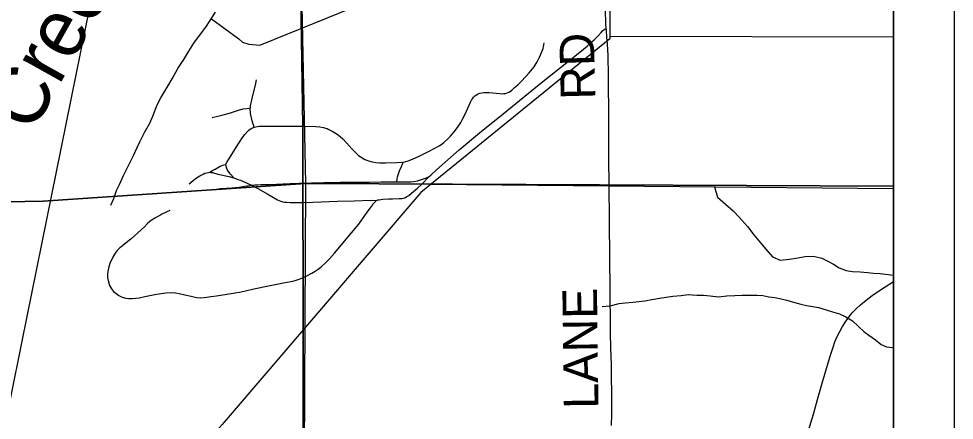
# Model space of a CAD drawing. Extents: x 0 to 34, y 0 to 22.
# Drawn here: x 7.463 to 9, y 15.878 to 16.538 of the extents above; entities that cross this region are included whole.
import ezdxf

# ---------------------------------------------------------------- set-up
doc = ezdxf.new("R2010")
doc.units = 0
for name, color, linetype in [('GM_X_County_Road', 7, 'Continuous'), ('GM_X_County_Road_Text', 7, 'Continuous'), ('GM_X_Major_River_Text', 7, 'Continuous'), ('GM_X_Minor_River', 7, 'Continuous'), ('GM_X_Rail_Line', 7, 'Continuous'), ('GM_X_Section', 7, 'Continuous'), ('GM_X_State_Route', 7, 'Continuous'), ('GM_X_Township_Road', 7, 'Continuous'), ('GM_X_Unincorporated', 7, 'Continuous'), ('SH_Data', 7, 'Continuous')]:
    doc.layers.add(name, color=color, linetype=linetype)

msp = doc.modelspace()

# ---------------------------------------------------------------- linework, layer by layer
at = {"layer": 'GM_X_County_Road'}
for points in [[(8.4282, 16.5223), (8.4276, 16.5297), (8.4273, 16.5364), (8.4269, 16.546), (8.4267, 16.5738), (8.4266, 16.6455), (8.4263, 16.7142), (8.4261, 16.7744)], [(8.4371, 15.8698), (8.4374, 15.8884), (8.4375, 15.9008), (8.4375, 15.9101), (8.4373, 15.9225), (8.4369, 15.9504), (8.4368, 15.9694), (8.436, 15.997), (8.4355, 16.0218), (8.4351, 16.0371), (8.435, 16.0556), (8.4348, 16.068), (8.4345, 16.0959), (8.434, 16.1425), (8.4335, 16.2076), (8.4332, 16.2635), (8.4326, 16.3101), (8.4326, 16.3721), (8.432, 16.4435), (8.4314, 16.4777), (8.4303, 16.4962), (8.4294, 16.5078), (8.4285, 16.5185), (8.4282, 16.5223)]]:
    msp.add_lwpolyline(points, dxfattribs=at)
at = {"layer": 'GM_X_Minor_River'}
for p, q in [((8.4339, 16.5096), (8.9, 16.5083)), ((8.1399, 16.2661), (8.9, 16.2594))]:
    msp.add_line(p, q, dxfattribs=at)
for points in [[(8.4344, 16.8906), (8.4339, 16.505), (8.1234, 16.2526), (7.7972, 15.8716), (7.3114, 15.3314), (7.166, 15.2871), (6.9088, 15.1189), (6.3982, 15.0073)], [(7.7796, 16.5378), (7.8248, 16.5051), (7.8305, 16.4998), (7.8411, 16.4965), (7.8593, 16.4947), (8.2339, 16.6471), (8.2403, 16.6506), (8.2527, 16.6612), (8.2735, 16.7521)], [(7.6143, 16.232), (7.6192, 16.2427), (7.6236, 16.2556), (7.6285, 16.2659), (7.6353, 16.2803), (7.6401, 16.2902), (7.6469, 16.3035), (7.6514, 16.3134), (7.6577, 16.3263), (7.6622, 16.3358), (7.6705, 16.3522), (7.6783, 16.3667), (7.6836, 16.3781), (7.6903, 16.3967), (7.6967, 16.4081), (7.7079, 16.4275), (7.7151, 16.4393), (7.7244, 16.4565), (7.7342, 16.4713), (7.7425, 16.485), (7.7507, 16.498), (7.7631, 16.5147), (7.7703, 16.5242), (7.7778, 16.5349), (7.7864, 16.549)], [(8.6059, 16.262), (8.6111, 16.2451), (8.6244, 16.2334), (8.6365, 16.2224), (8.6464, 16.2118), (8.6601, 16.1967), (8.6708, 16.1831), (8.6818, 16.1699), (8.6906, 16.1597), (8.7016, 16.1468), (8.7141, 16.1416), (8.7292, 16.1431), (8.7398, 16.1447), (8.7549, 16.1474), (8.7689, 16.1479), (8.7822, 16.1445), (8.792, 16.1396), (8.8015, 16.1348), (8.811, 16.1291), (8.8224, 16.1246), (8.833, 16.1228), (8.8455, 16.1221), (8.8576, 16.121), (8.8674, 16.1199), (8.878, 16.1196), (8.9, 16.1169)], [(8.4217, 16.0653), (8.4346, 16.0663), (8.4494, 16.0704), (8.4596, 16.0712), (8.4717, 16.0726), (8.4819, 16.0737), (8.4917, 16.0744), (8.5031, 16.0766), (8.5163, 16.0788), (8.5269, 16.0807), (8.5375, 16.0822), (8.5511, 16.0832), (8.5629, 16.0851), (8.5768, 16.0842), (8.5882, 16.0842), (8.5992, 16.083), (8.6128, 16.0814), (8.6264, 16.0829), (8.6396, 16.0836), (8.6513, 16.0839), (8.6634, 16.0838), (8.6755, 16.0841), (8.6854, 16.0833), (8.6956, 16.0814), (8.705, 16.0802), (8.7156, 16.0779), (8.7251, 16.0755), (8.736, 16.0724), (8.7477, 16.0694), (8.7572, 16.067), (8.7674, 16.0651), (8.7768, 16.0635), (8.7893, 16.0597), (8.8002, 16.0566), (8.8116, 16.0531), (8.8218, 16.0481), (8.8327, 16.0416), (8.8433, 16.0321), (8.8512, 16.0245), (8.8598, 16.0183), (8.8704, 16.0103), (8.8798, 16.0031), (8.8889, 15.9988), (8.8983, 15.9977), (8.9, 15.9974)]]:
    msp.add_lwpolyline(points, dxfattribs=at)
at = {"layer": 'GM_X_Rail_Line'}
msp.add_lwpolyline([(6.4606, 14.1), (6.4571, 14.1954), (6.4477, 14.4405), (6.4524, 14.5081), (6.4637, 14.5568), (6.4857, 14.6083), (6.5473, 14.6979), (6.8861, 15.1309), (7.2406, 15.5724), (7.3338, 15.6825), (7.3851, 15.7562), (7.4225, 15.8224), (7.4495, 15.9132), (7.4686, 16.0084), (7.5816, 16.5648), (7.6436, 16.8869), (7.6684, 17.0095), (7.6975, 17.0913), (7.758, 17.2454), (8.0083, 17.8807), (8.1494, 18.2455), (8.2773, 18.5592), (8.2934, 18.6184), (8.454, 19.2815)], dxfattribs=at)
at = {"layer": 'GM_X_Section'}
for points in [[(6.9237, 17.2428), (7.9201, 17.2543), (7.92, 16.958), (7.9341, 16.2671), (7.503, 16.2382), (6.9303, 16.2282)], [(7.9341, 16.2671), (7.9294, 15.2601), (6.9531, 15.2604), (6.9228, 15.2602), (6.9303, 16.2282), (7.503, 16.2382)]]:
    msp.add_lwpolyline(points, close=True, dxfattribs=at)
at = {"layer": 'GM_X_State_Route'}
msp.add_lwpolyline([(8.7579, 15.8529), (8.7685, 15.8886), (8.7755, 15.9124), (8.7832, 15.9393), (8.7962, 15.9839), (8.8008, 15.9987), (8.804, 16.0074), (8.8077, 16.0158), (8.8118, 16.0241), (8.8164, 16.0322), (8.8213, 16.0401), (8.8266, 16.0476), (8.8325, 16.0548), (8.8389, 16.0615), (8.8457, 16.0678), (8.8552, 16.0758), (8.865, 16.0832), (8.8804, 16.0937), (8.9, 16.1066)], dxfattribs=at)
at = {"layer": 'GM_X_Township_Road'}
for points in [[(5.7675, 15.2711), (6.9226, 15.2644), (7.9283, 15.2595), (7.9306, 15.7658), (7.9301, 16.1134), (7.9298, 16.2367), (7.9298, 16.2686), (7.9297, 16.3619), (7.9163, 17.252), (8.4218, 17.2637), (8.9, 17.2634), (8.9, 20.9)], [(7.9303, 16.1128), (7.9366, 16.1156), (7.9448, 16.1199), (7.9502, 16.1231), (7.9552, 16.1267), (7.9601, 16.1306), (7.9669, 16.1369), (7.9735, 16.1436), (7.9817, 16.1529), (8.0099, 16.1861), (8.0216, 16.2006), (8.0317, 16.2146), (8.0361, 16.2207), (8.0406, 16.2271), (8.0429, 16.2303), (8.0455, 16.2338), (8.0478, 16.2363), (8.0489, 16.2375), (8.0498, 16.2384), (8.051, 16.2397), (8.0531, 16.2403), (8.0552, 16.2407), (8.0582, 16.2412), (8.0615, 16.2415), (8.0709, 16.2421), (8.0771, 16.2423), (8.0882, 16.2428), (8.0925, 16.243), (8.0953, 16.2435), (8.0983, 16.2446), (8.1007, 16.2458), (8.1037, 16.2478), (8.1086, 16.2515), (8.118, 16.2595), (8.1249, 16.2658), (8.1374, 16.2786), (8.1401, 16.2813), (8.1492, 16.2897), (8.1867, 16.3224), (8.22, 16.3505), (8.2589, 16.3817), (8.3215, 16.4328), (8.3847, 16.483), (8.3907, 16.4878), (8.3971, 16.4931), (8.4015, 16.4972), (8.4084, 16.5035), (8.4149, 16.5102), (8.4198, 16.5156), (8.4222, 16.5181), (8.4248, 16.5202), (8.4266, 16.5215), (8.4282, 16.5223)], [(7.9299, 16.3614), (7.9328, 16.3613), (7.9514, 16.3609), (7.9576, 16.3603), (7.9637, 16.3593), (7.9668, 16.3585), (7.9697, 16.3575), (7.9726, 16.3563), (7.9781, 16.3534), (7.986, 16.3484), (7.9909, 16.3446), (7.9956, 16.3405), (8.002, 16.3337), (8.0102, 16.3244), (8.0168, 16.3177), (8.0214, 16.3136), (8.0239, 16.3117), (8.0265, 16.3099), (8.0291, 16.3084), (8.0319, 16.3069), (8.0348, 16.3057), (8.0377, 16.3046), (8.0437, 16.3031), (8.0499, 16.3021), (8.0561, 16.3015), (8.0654, 16.3014), (8.0841, 16.3017), (8.0934, 16.3023), (8.0945, 16.3024), (8.099, 16.3035), (8.103, 16.3047), (8.1097, 16.3071), (8.1222, 16.3128), (8.1331, 16.3183), (8.1373, 16.3204), (8.1457, 16.3246), (8.1539, 16.3293), (8.1565, 16.3309), (8.1613, 16.3345), (8.1681, 16.3406), (8.1724, 16.345), (8.1785, 16.3521), (8.1841, 16.3596), (8.1892, 16.3676), (8.1922, 16.373), (8.1964, 16.3814), (8.2053, 16.4012), (8.2068, 16.404), (8.2084, 16.4066), (8.2104, 16.4091), (8.2126, 16.4112), (8.215, 16.4131), (8.2178, 16.4145), (8.2207, 16.4156), (8.2238, 16.4162), (8.2269, 16.4167), (8.23, 16.4168), (8.2359, 16.4167), (8.2532, 16.415), (8.2564, 16.4149), (8.2595, 16.415), (8.2625, 16.4154), (8.2654, 16.4163), (8.2682, 16.4175), (8.2707, 16.4191), (8.2734, 16.4209), (8.2778, 16.4248), (8.2831, 16.4296), (8.2883, 16.4349), (8.2961, 16.4433), (8.3018, 16.4493), (8.3097, 16.459), (8.3146, 16.467), (8.3188, 16.475), (8.3224, 16.4834), (8.3244, 16.4892), (8.3252, 16.4922), (8.3258, 16.4952), (8.3262, 16.4982)], [(7.8499, 16.36), (7.8485, 16.3638), (7.8477, 16.3667), (7.8467, 16.3703), (7.8441, 16.3821), (7.8436, 16.3853), (7.8434, 16.3884), (7.8437, 16.3915), (7.8439, 16.3947), (7.8466, 16.407), (7.8525, 16.4317), (7.8537, 16.4378)], [(7.7809, 16.3758), (7.7901, 16.3778), (7.7991, 16.38), (7.811, 16.3837), (7.8258, 16.3884), (7.8319, 16.3898), (7.838, 16.3907), (7.8437, 16.3915)], [(7.7768, 16.2862), (7.7813, 16.2885), (7.7836, 16.2897), (7.7859, 16.291), (7.7942, 16.2956), (7.7972, 16.2968), (7.8002, 16.298), (7.8031, 16.2986), (7.8046, 16.3011), (7.8094, 16.3088), (7.8207, 16.3275), (7.8308, 16.3431), (7.8345, 16.3481), (7.8387, 16.3527), (7.8411, 16.3548), (7.8435, 16.3567), (7.8462, 16.3583), (7.8499, 16.36), (7.8527, 16.3607), (7.8552, 16.3611), (7.8581, 16.3613), (7.8612, 16.3616), (7.869, 16.3618), (7.8984, 16.3616), (7.9299, 16.3614)], [(7.8165, 16.2769), (7.8111, 16.2827), (7.8093, 16.2851), (7.8074, 16.2877), (7.8057, 16.2905), (7.8046, 16.2935), (7.8036, 16.2963), (7.8031, 16.2986)], [(8.0844, 16.2701), (8.0847, 16.275), (8.0853, 16.2784), (8.0865, 16.2818), (8.0887, 16.2881), (8.0918, 16.2952), (8.0925, 16.297), (8.0933, 16.299), (8.0945, 16.3024)], [(7.7432, 16.2668), (7.7527, 16.275), (7.7552, 16.2768), (7.7605, 16.2801), (7.7661, 16.2829), (7.769, 16.2841), (7.772, 16.285), (7.7746, 16.2857), (7.7768, 16.2862), (7.7789, 16.2857), (7.7812, 16.2852), (7.7903, 16.2829), (7.8086, 16.2787), (7.8143, 16.2772), (7.8165, 16.2769), (7.8231, 16.2742), (7.8272, 16.2727), (7.8457, 16.2646), (7.8481, 16.2635), (7.8506, 16.2621), (7.8559, 16.2591), (7.8721, 16.2501), (7.8882, 16.2408), (7.891, 16.2394), (7.8938, 16.2383), (7.8968, 16.2375), (7.8998, 16.2369), (7.9029, 16.2365), (7.909, 16.2362), (7.93, 16.2362)], [(7.929, 16.268), (7.93, 16.2681), (7.9316, 16.2681), (7.9441, 16.2686), (7.9533, 16.2687), (7.9642, 16.2689), (7.9799, 16.2692), (7.9914, 16.2693), (7.9984, 16.2694), (8.0089, 16.2696), (8.0161, 16.2697), (8.0306, 16.2697), (8.0387, 16.2698), (8.058, 16.2699), (8.0687, 16.2701), (8.0773, 16.27), (8.0844, 16.2701), (8.0964, 16.2699), (8.1015, 16.2701), (8.1074, 16.2702), (8.1122, 16.2706), (8.118, 16.2719), (8.1233, 16.2734), (8.128, 16.2751), (8.1328, 16.2769), (8.1374, 16.2786)], [(7.7853, 16.2577), (7.7946, 16.2589), (7.8131, 16.2604), (7.825, 16.2616), (7.8338, 16.2628), (7.8426, 16.2641), (7.8457, 16.2646), (7.8512, 16.2652), (7.8559, 16.2654), (7.8607, 16.2657), (7.8748, 16.2659), (7.9088, 16.2673), (7.9232, 16.2678), (7.929, 16.268)], [(7.93, 16.2362), (7.9307, 16.2362), (7.9462, 16.2368), (7.9865, 16.2384), (8.0144, 16.2391), (8.0418, 16.2399), (8.051, 16.2397)], [(7.7113, 16.2229), (7.6983, 16.2169), (7.6949, 16.2146), (7.6916, 16.2129), (7.6869, 16.2103), (7.6824, 16.2079), (7.6783, 16.205), (7.6747, 16.2014), (7.6697, 16.1962), (7.6588, 16.1864), (7.6527, 16.1811), (7.6471, 16.176), (7.6397, 16.1697), (7.6335, 16.1648), (7.6294, 16.1615), (7.625, 16.1571), (7.6217, 16.153), (7.6184, 16.1475), (7.6159, 16.1425), (7.6133, 16.1376), (7.6113, 16.1303), (7.6099, 16.1254), (7.6092, 16.1197), (7.6092, 16.1132), (7.6098, 16.1079), (7.6121, 16.1), (7.6153, 16.0946), (7.6187, 16.09), (7.6224, 16.0871), (7.6278, 16.0835), (7.6331, 16.0809), (7.6389, 16.0792), (7.6441, 16.0785), (7.6494, 16.0785), (7.6555, 16.0791), (7.6609, 16.0798), (7.6703, 16.0816), (7.6866, 16.0851), (7.697, 16.0869), (7.7048, 16.0879), (7.7143, 16.0883), (7.7206, 16.0876), (7.7265, 16.0867), (7.7359, 16.0846), (7.7464, 16.0821), (7.7549, 16.0801), (7.7619, 16.0796), (7.7676, 16.0799), (7.7721, 16.0805), (7.7788, 16.0817)], [(7.7788, 16.0817), (7.788, 16.083), (7.8188, 16.0877), (7.8255, 16.089), (7.8307, 16.09), (7.8359, 16.091), (7.8492, 16.0941), (7.8735, 16.0995), (7.901, 16.1047), (7.9132, 16.1072), (7.9171, 16.1081), (7.9222, 16.1097), (7.928, 16.1118), (7.9303, 16.1128)]]:
    msp.add_lwpolyline(points, dxfattribs=at)
msp.add_lwpolyline([(5.7705, 14.1), (8.9, 14.1), (8.9, 17.2634), (8.4218, 17.2637), (7.9163, 17.252), (7.9297, 16.3619), (7.9298, 16.2686), (7.9298, 16.2367), (7.9301, 16.1134), (7.9306, 15.7658), (7.9283, 15.2595), (6.9226, 15.2644), (5.7675, 15.2711), (5.7694, 14.855)], close=True, dxfattribs=at)
at = {"layer": 'GM_X_Unincorporated'}
for points in [[(8.9, 16.2628), (8.9, 17.263), (7.9201, 17.2543), (7.92, 16.958), (7.9341, 16.2671)], [(8.9, 15.2555), (8.9, 16.2628), (7.9341, 16.2671), (7.9294, 15.2601), (7.9571, 15.2595)]]:
    msp.add_lwpolyline(points, close=True, dxfattribs=at)
at = {"layer": 'SH_Data'}
for p, q in [((9, 21), (9, 14)), ((8.9, 20.9), (8.9, 14.1))]:
    msp.add_line(p, q, dxfattribs=at)

# ---------------------------------------------------------------- texts
at = {"layer": 'GM_X_County_Road_Text'}
for s, rotation, p in [('RD', 91.4141, (8.4105, 16.4058)), ('LANE', 90.7332, (8.4155, 15.8976))]:
    msp.add_text(s, height=0.05682, rotation=rotation, dxfattribs=at).set_placement(p)
at = {"layer": 'GM_X_Major_River_Text'}
msp.add_text('Creek', height=0.09472, rotation=60.7664, dxfattribs=at).set_placement((7.4844, 16.3473))

doc.saveas('drawing.dxf')
